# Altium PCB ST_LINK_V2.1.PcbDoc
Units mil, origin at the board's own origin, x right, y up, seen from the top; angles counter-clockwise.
Board outline 1520 x 655 mil, 2 copper layers (Top Layer, Bottom Layer); 53 components, 47 nets, 184 pads, 65 vias.
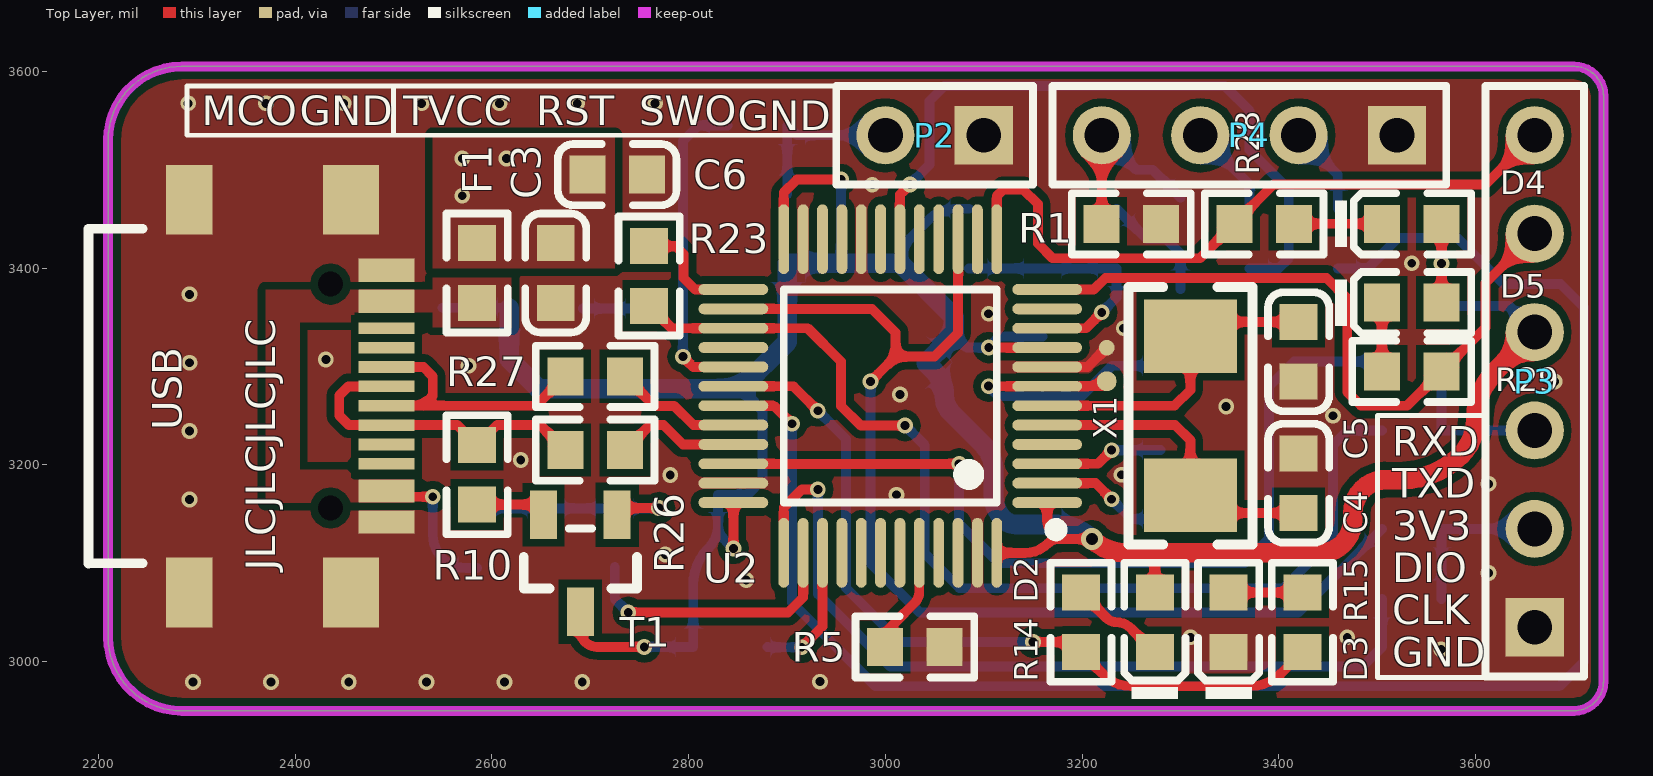
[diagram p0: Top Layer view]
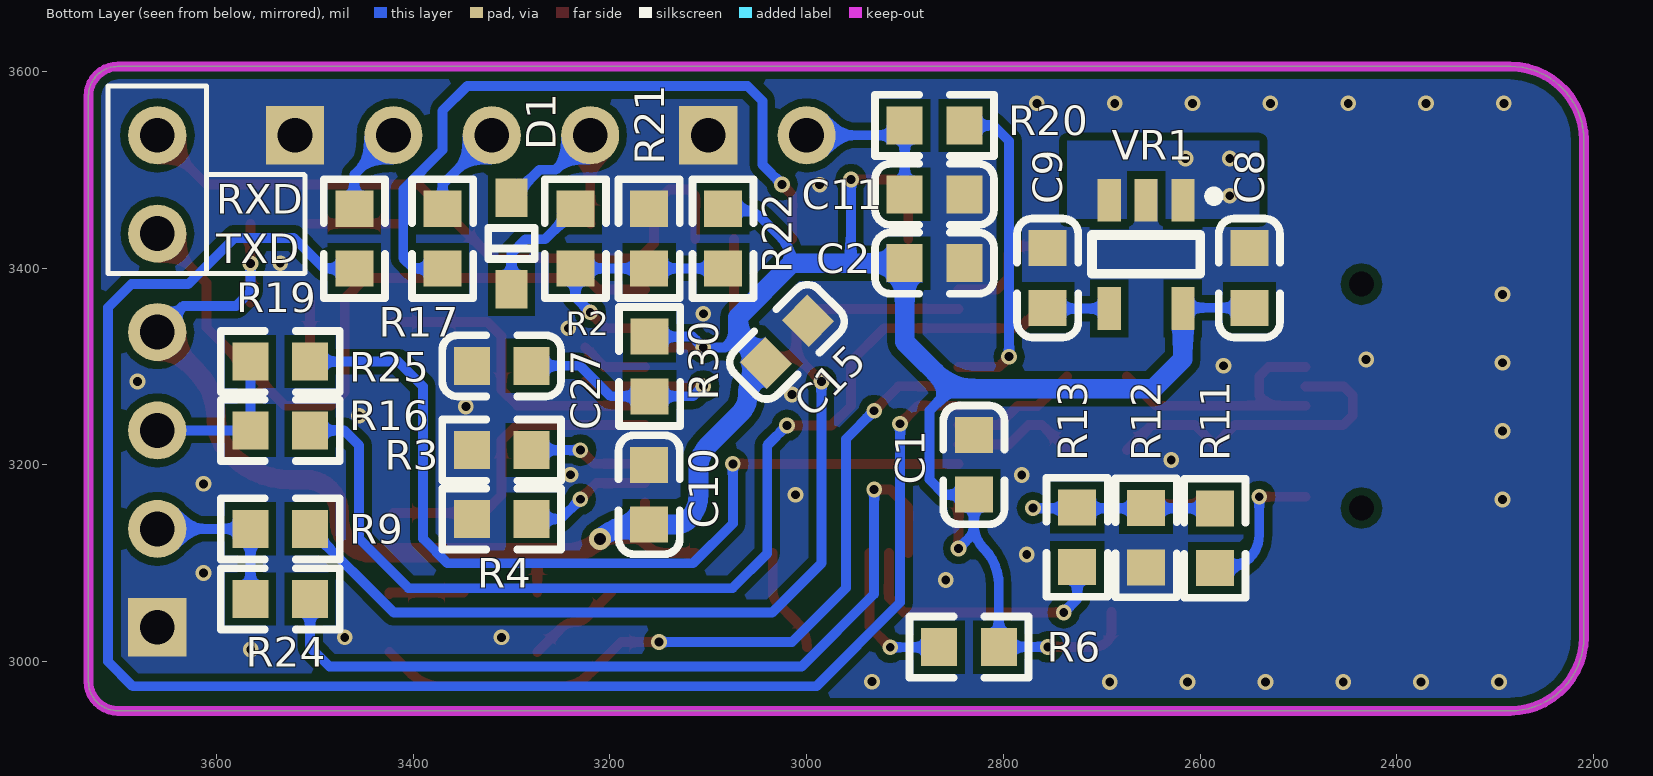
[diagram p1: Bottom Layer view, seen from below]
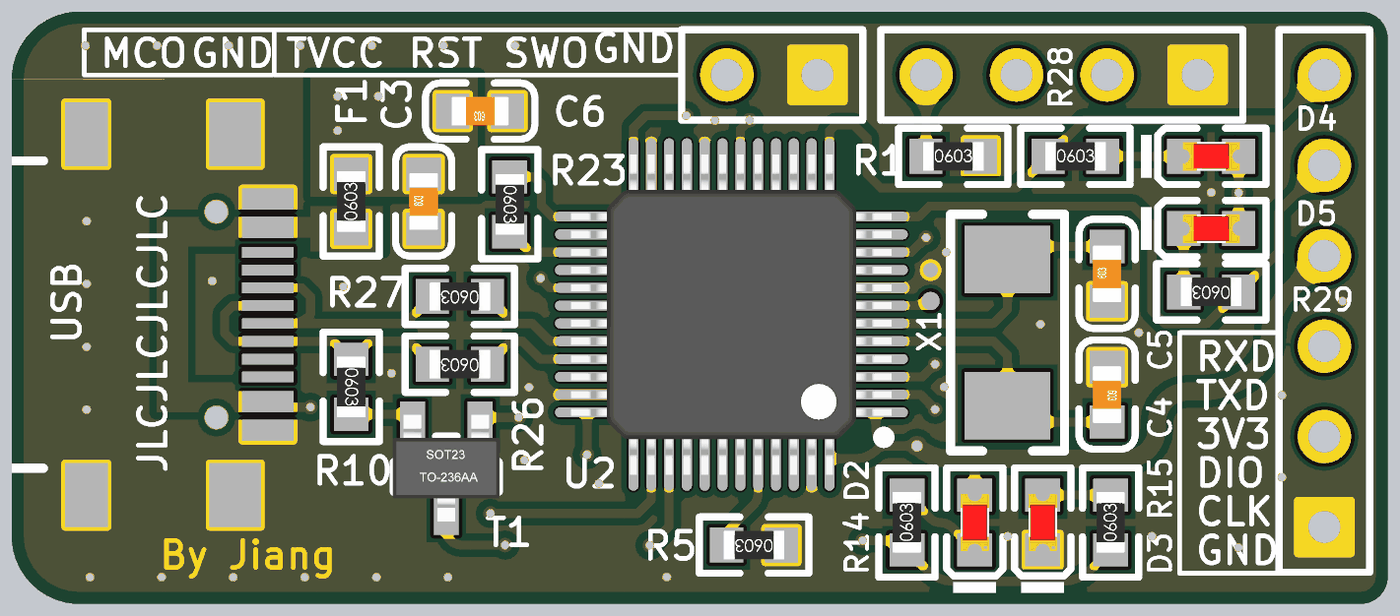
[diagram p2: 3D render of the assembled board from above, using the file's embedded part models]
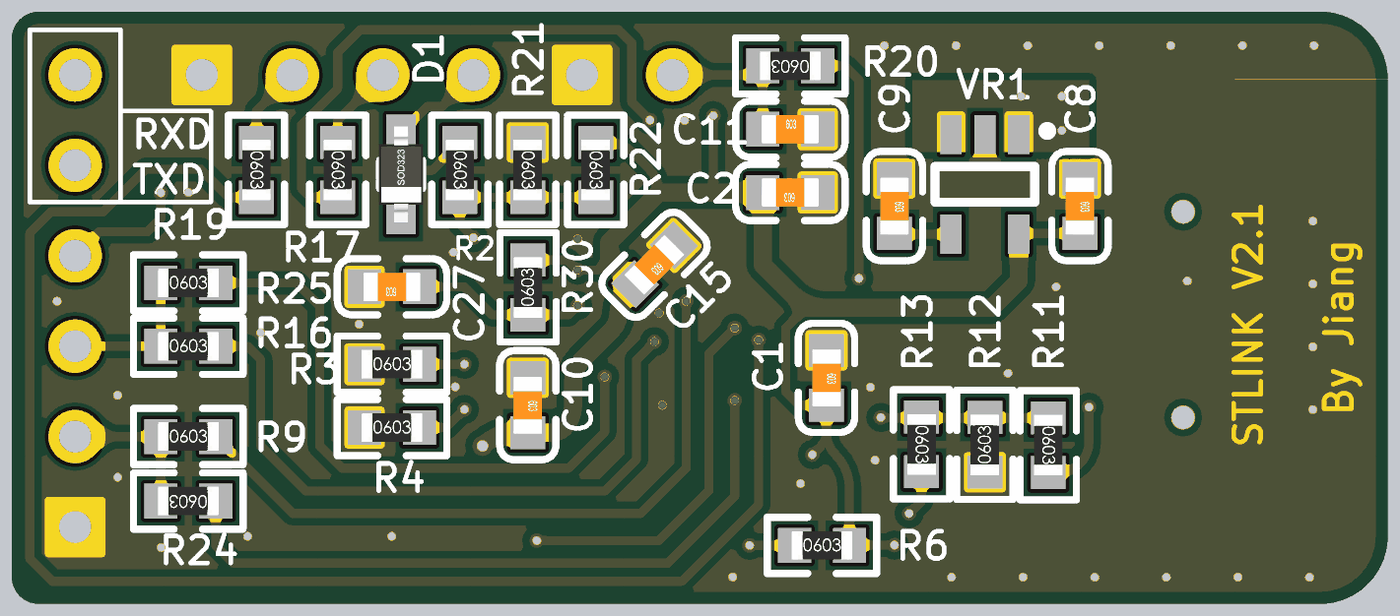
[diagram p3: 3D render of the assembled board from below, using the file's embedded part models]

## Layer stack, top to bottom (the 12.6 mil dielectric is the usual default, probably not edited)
Top Solder: solder mask 0.4, Solder Resist, Dk 3.5
Top Layer: signal copper 1.4
Dielectric 1: dielectric 12.6, FR-4, Dk 4.8
Bottom Layer: signal copper 1.4
Bottom Solder: solder mask 0.4, Solder Resist, Dk 3.5

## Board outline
2285,2950 cw(c2285,3025) 2210,3025 2210,3530 cw(c2285,3530) 2285,3605 3700,3605 cw(c3700,3575) 3730,3575 3730,2980 cw(c3700,2980) 3700,2950

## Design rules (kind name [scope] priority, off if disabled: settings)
Clearance [All] p1: gap=8 ignorepadtopadclearanceinfootprint=TRUE except(0: Arc-Hole Track-Hole SMDPad-Hole THPad-Hole Via-Hole Fill-Hole Poly-Hole Region-Hole Text-Hole)
PolygonConnect PolygonConnect_8 [All vs IsNamedPolygon('Top Layer-5V_USB_CHG 1') Or  IsNamedPolygon('Top Layer-5V_USB_CHG') Or  IsNamedPolygon('Bottom Layer-5V_USB_CHG') Or  IsNamedPolygon('Bottom Layer-GND') Or  IsNamedPolygon('Top Layer-GND') Or  IsNamedPolygon('Top Layer-5V_USB_CHG 2')] p1: connectstyle=Direct reliefconductorwidth=10 reliefentries=4 polygonreliefangle="90 Angle" airgapwidth=10
PolygonConnect PolygonConnect_7 [All vs IsNamedPolygon('Top Layer-5V_USB_CHG 2')] p2: connectstyle=Direct reliefconductorwidth=10 reliefentries=4 polygonreliefangle="90 Angle" airgapwidth=10
PolygonConnect PolygonConnect_6 [All vs IsNamedPolygon('Top Layer-5V_USB_CHG 1')] p3: connectstyle=Direct reliefconductorwidth=10 reliefentries=4 polygonreliefangle="90 Angle" airgapwidth=10
PolygonConnect PolygonConnect_5 [All vs IsNamedPolygon('Top Layer-No Net') Or  IsNamedPolygon('Top Layer-5V_USB_CHG') Or  IsNamedPolygon('Bottom Layer-No Net') Or  IsNamedPolygon('Bottom Layer-5V_USB_CHG') Or  IsNamedPolygon('Top Layer-5V_USB_CHG 2')] p4: connectstyle=Direct reliefconductorwidth=10 reliefentries=4 polygonreliefangle="90 Angle" airgapwidth=10
PolygonConnect PolygonConnect_4 [All vs IsNamedPolygon('Top Layer-5V_USB_CHG 2')] p5: connectstyle=Direct reliefconductorwidth=10 reliefentries=4 polygonreliefangle="90 Angle" airgapwidth=10
PolygonConnect PolygonConnect_3 [All vs IsNamedPolygon('Top Layer-5V_USB_CHG 1') Or  IsNamedPolygon('Top Layer-5V_USB_CHG') Or  IsNamedPolygon('Bottom Layer-5V_USB_CHG')] p6: connectstyle=Direct reliefconductorwidth=10 reliefentries=4 polygonreliefangle="90 Angle" airgapwidth=10
PolygonConnect PolygonConnect_2 [All vs IsNamedPolygon('Top Layer-5V_USB_CHG') Or  IsNamedPolygon('Top Layer-5V_USB_CHG 1')] p7: connectstyle=Direct reliefconductorwidth=10 reliefentries=4 polygonreliefangle="90 Angle" airgapwidth=10
PolygonConnect PolygonConnect_1 [All vs IsNamedPolygon('Top Layer-5V_USB_CHG 1') Or  IsNamedPolygon('Top Layer-5V_USB_CHG')] p8: connectstyle=Direct reliefconductorwidth=10 reliefentries=4 polygonreliefangle="90 Angle" airgapwidth=10
PolygonConnect [All] p9: connectstyle=Relief reliefconductorwidth=10 reliefentries=4 polygonreliefangle="90 Angle" airgapwidth=10
RoutingVias [All] p1: holewidth=28 width=50 viastyle="Through Hole" minholewidth=28 minwidth=50 maxholewidth=28 maxwidth=50
SolderMaskExpansion [All] p1: expansion=4
Width [All] p1: maxlimit=50 minlimit=10 preferedwidth=10
30 further rules are at their usual default settings.

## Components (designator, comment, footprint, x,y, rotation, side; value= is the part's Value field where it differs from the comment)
C1 "Capacitor" 0603_C 2830,3200 r270 bottom value=100nF
C2 "Capacitor" 0603_C 2870,3405 r0 bottom value=100nF
C3 "104" 0603_C 2665,3395 r90 top
C4 "Capacitor" 0603_C 3420,3181.42 r270 top value=20pF
C5 "Capacitor" 0603_C 3420,3315 r90 top value=20pF
C6 "104" 0603_C 2727.4,3495 r180 top
C8 "104" 0603_C 2550,3390 r270 bottom
C9 "104" 0603_C 2755,3390 r270 bottom
C10 "Capacitor" 0603_C 3160,3169.69 r270 bottom value=100nF
C11 "20pF" 0603_C 2870,3475 r180 bottom
C15 "Capacitor" 0603_C 3020,3325 r315 bottom value=100nF
C27 "Capacitor" 0603_C 3310,3300.68 r0 bottom value=103
D1 "BAT60JFILM" SOD-323 3300,3425 r90 bottom
D2 "绿灯 0603" 0603_LED_S1 3273.86,3040 r90 top
D3 "红灯 0603" 0603_LED_S1 3348.86,3040 r90 top
D4 "红灯 0603" 0603_LED_S1 3535,3445 r0 top
D5 "红灯 0603" 0603_LED_S1 3535,3365 r0 top
F1 "Fuse 2" 0603_R 2585,3395 r90 top
P2 "Header 2" HDR1X2 3100,3535 r180 top
P3 "Header 6" HDR1X6 3660,3035 r90 top
P4 "Header 4" HDR1X4 3520,3535 r180 top
R1 "Resistor" 0603_R 3250,3445 r0 top value=10K
R2 "100R" 0603_R 3235,3430 r270 bottom value=22R
R3 "N/A" 0603_R 3310,3215 r180 bottom value=10K
R4 "Resistor" 0603_R 3310,3145 r180 bottom value=10K
R5 "Resistor" 0603_R 3030,3015 r180 top value=100K
R6 "Resistor" 0603_R 2835,3014.69 r180 bottom value=4.7K
R9 "Resistor" 0603_R 3535,3135 r180 bottom value=22R
R10 "Resistor" 0603_R 2585,3190 r270 top value=1K5
R11 "Resistor" 0603_R 2585,3125.47 r270 bottom value=10K
R12 "Resistor" 0603_R 2655,3125.94 r90 bottom value=36K
R13 "Resistor" 0603_R 2725,3126.42 r270 bottom value=100R
R14 "Resistor" 0603_R 3198.86,3040 r90 top value=330R
R15 "Resistor" 0603_R 3423.86,3040 r90 top value=330R
R16 "Resistor" 0603_R 3535,3235 r180 bottom value=22R
R17 "Resistor" 0603_R 3370,3430 r270 bottom value=22R
R19 "Resistor" 0603_R 3459.74,3430 r270 bottom value=22R
R20 "Resistor" 0603_R 2870,3545 r0 bottom value=100R
R21 "Resistor" 0603_R 3160,3430 r270 bottom value=4K7
R22 "Resistor" 0603_R 3085,3430 r270 bottom value=4K7
R23 "Resistor" 0603_R 2760,3391.97 r270 top value=100R
R24 "Resistor" 0603_R 3535,3063.74 r0 bottom value=0R
R25 "Resistor" 0603_R 3535,3305 r180 bottom value=0R
R26 "Resistor" 0603_R 2705,3215 r180 top value=10R
R27 "Resistor" 0603_R 2705,3290 r180 top value=10R
R28 "Resistor" 0603_R 3385,3445 r0 top value=1K
R29 "Resistor" 0603_R 3535,3295 r180 top value=1K
R30 "Resistor" 0603_R 3159.69,3300 r90 bottom value=10K
T1 "9013-SOT23" SOT-23(SOT-23-3) 2690,3100 r90 top
U2 "STM32F103CBT6" LQFP-48_7x7x05P 3005,3270 r90 top locked
USB "TYPE-C 12P" "TYPE-C 12P 贴片" 2190,3440 r270 top locked
VR1 "SPX3819M5-L-3-3" SOT-23-5 2655,3414.02 r90 bottom
X1 "XTAL_8M_NX3225GD" SMD-5032_2P 3310,3250 r90 top locked value=8.00Mhz

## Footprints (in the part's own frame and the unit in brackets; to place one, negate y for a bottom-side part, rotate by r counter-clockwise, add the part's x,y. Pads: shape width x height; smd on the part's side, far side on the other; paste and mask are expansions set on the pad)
0603_C [mm]
  rect 0.93x0.98 smd: 1(-0.77,0) 2(0.77,0)
  silkscreen extent -1.53,-0.79 1.54,0.79, body extent -0.8,-0.4 0.8,0.4, height 0.3
0603_LED_S1 [mm]
  rect 0.93x0.98 smd: A(0.77,0) K(-0.77,0)
  silkscreen extent -1.98,-0.79 1.54,0.79, body extent -0.8,-0.4 0.8,0.4, height 0.6
0603_R [mm]
  rect 0.93x0.98 smd: 1(-0.77,0) 2(0.77,0)
  silkscreen extent -1.53,-0.79 1.54,0.79, body extent -0.85,-0.4 0.85,0.4, height 0.56
HDR1X2 [mm] "Connector; Header; 2 Position"
  rect 1.5x1.5 hole 0.9: 1(0,0)
  round 1.5 hole 0.9: 2(2.54,0)
  silkscreen extent -1.27,-1.27 3.81,1.27
HDR1X4 [mm] "Connector; Header; 4 Position"
  rect 1.5x1.5 hole 0.9: 1(0,0)
  round 1.5 hole 0.9: 2(2.54,0) 3(5.08,0) 4(7.62,0)
  silkscreen extent -1.27,-1.27 8.89,1.27
HDR1X6 [mm] "Connector; Header; 6 Position"
  rect 1.5x1.5 hole 0.9: 1(0,0)
  round 1.5 hole 0.9: 2(2.54,0) 3(5.08,0) 4(7.62,0) 5(10.16,0) 6(12.7,0)
  silkscreen extent -1.27,-1.27 13.97,1.27
LQFP-48_7x7x05P [mm]
  oval 0.28x1.8 smd mask+0.051: 1(-2.75,-4.05) 2(-2.25,-4.05) 3(-1.75,-4.05) 4(-1.25,-4.05) 5(-0.75,-4.05) 6(-0.25,-4.05) 7(0.25,-4.05) 8(0.75,-4.05) 9(1.25,-4.05) 10(1.75,-4.05) 11(2.25,-4.05) 12(2.75,-4.05) 25(2.75,4.05) 26(2.25,4.05) 27(1.75,4.05) 28(1.25,4.05) 29(0.75,4.05) 30(0.25,4.05) 31(-0.25,4.05) 32(-0.75,4.05) 33(-1.25,4.05) 34(-1.75,4.05) 35(-2.25,4.05) 36(-2.75,4.05)
  oval 1.8x0.28 smd mask+0.051: 13(4.05,-2.75) 14(4.05,-2.25) 15(4.05,-1.75) 16(4.05,-1.25) 17(4.05,-0.75) 18(4.05,-0.25) 19(4.05,0.25) 20(4.05,0.75) 21(4.05,1.25) 22(4.05,1.75) 23(4.05,2.25) 24(4.05,2.75) 37(-4.05,2.75) 38(-4.05,2.25) 39(-4.05,1.75) 40(-4.05,1.25) 41(-4.05,0.75) 42(-4.05,0.25) 43(-4.05,-0.25) 44(-4.05,-0.75) 45(-4.05,-1.25) 46(-4.05,-1.75) 47(-4.05,-2.25) 48(-4.05,-2.75)
  silkscreen extent -3.6,-4.42 2.75,2.75, body extent -4.5,-4.5 4.5,4.5, height 1.6
SMD-5032_2P [mm]
  rect 1.9x2.4 smd: 1(-2.05,0) 2(2.05,0)
  silkscreen extent -3.32,-1.6 3.32,1.6
SOD-323 [mm]
  rect 1x0.83 smd: 1(1.18,0) 2(-1.18,0)
  silkscreen extent -0.4,-0.6 0.4,0.6, body extent -1.35,-0.63 1.35,0.63, height 1.1
SOT-23(SOT-23-3) [mm]
  rect 1.25x0.7 smd: 1(1.25,-0.95) 2(1.25,0.95) 3(-1.25,0)
  silkscreen extent -0.65,-1.46 0.9,1.46, body extent -1.5,-1.5 1.5,1.5, height 1.3
SOT-23-5 [mm]
  rect 1.1x0.6 smd: 1(1.4,-0.95) 2(1.4,0) 3(1.4,0.95) 4(-1.4,0.95) 5(-1.4,-0.95)
  silkscreen extent -0.5,-1.87 1.62,1.4
"TYPE-C 12P 贴片" [mm]
  rect 1.8x1.45 smd: 0(-0.75,6.78) 0(9.39,6.78)
  rect 1.8x1.2 smd: 0(-0.75,2.6) 0(9.39,2.6)
  round 0 hole 0.65: 5(1.43,6.25) 5(7.21,6.25)
  rect 0.3x1.45 smd: A1(0.92,7.695) A4(1.72,7.695) A5(3.07,7.695) A6(4.07,7.695) A7(4.57,7.695) A8(5.57,7.695) A9(6.92,7.695) A12(7.72,7.695) B1(7.42,7.695) B4(6.62,7.695) B5(6.07,7.695) B6(5.07,7.695) B7(3.57,7.695) B8(2.57,7.695) B9(2.02,7.695) B12(1.22,7.695)
  silkscreen extent 0,0 8.64,1.4, body extent 0,0 8.64,8, height 3.21

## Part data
C1 C2 C10 C15 C27: library part MCD-00211, "Capacitor, MLCC, 100nF, 16V, X7R, 10%, 0603, T=0,8mm", Manufacturer=YAGEO, Manufacturer_Part_Number=CC0603KRX7R7BB104, Package=C0603
C3 C6 C8 C9: library part "0603 2.7pF (2R7) 0.25pF 50V", "贴片电容", Package=0603, SuppliersPartNumber=C16149
C4 C5: library part MCD-00637, "Capacitor, MLCC, 10pF, 50V, NPO, 5%, 0603, T=0,8mm", Manufacturer=YAGEO, Manufacturer_Part_Number=CC0603JRNPO9BN100, Package=C0603
C11: library part MCD-00638, "Capacitor, MLCC, 20pF, 50V, NPO, 5%, 0603, T=0,8mm", Manufacturer=YAGEO, Manufacturer_Part_Number=CC0603JRNPO9BN200, Package=C0603
D1: library part MCD-00034, Manufacturer=STMICROELECTRONICS
D2: library part "0603 绿灯", "发光二极管", Package=0603, SuppliersPartNumber=C72043
D3 D4 D5: library part "0603 红灯", "发光二极管", Package=0603, SuppliersPartNumber=C2286
F1: "Fuse"
P2: "Header, 2-Pin"
P3: "Header, 6-Pin"
P4: "Header, 4-Pin"
R1 R3 R4 R11: library part MCD-00220, "Resistor,10K,0603,1%,1/10W", Manufacturer=YAGEO, Manufacturer_Part_Number=RC0603FR-0710KL, Package=R0603
R2 R9 R16 R17 R19 R24 R25: library part MCD-00066, "Resistor,22R,0603,1%,1/10W", Manufacturer=YAGEO, Manufacturer_Part_Number=RC0603FR-0722RL, Package=R0603
R5 R30: library part MCD-00223, "Resistor,100K,0603,1%,1/10W", Manufacturer=YAGEO, Manufacturer_Part_Number=RC0603FR-07100KL, Package=R0603
R6 R14 R15 R28 R29: library part MCD-00197, "Resistor,330R,0603,1%,1/10W", Manufacturer=YAGEO, Manufacturer_Part_Number=RC0603FR-07330RL, Package=R0603
R10: library part MCD-00217, "Resistor,1K5,0603,1%,1/10W", Manufacturer=YAGEO, Manufacturer_Part_Number=RC0603FR-071K5L, Package=R0603
R12: library part MCD-00221, "Resistor,36K,0603,1%,1/10W", Manufacturer=YAGEO, Manufacturer_Part_Number=RC0603FR-0736KL, Package=R0603
R13 R20 R23 R26 R27: library part MCD-00224, "Resistor,100R,0603,1%,1/10W", Manufacturer=YAGEO, Manufacturer_Part_Number=RC0603FR-07100RL, Package=R0603
R21 R22: library part MCD-00219, "Resistor,4K7,0603,1%,1/10W", Manufacturer=YAGEO, Manufacturer_Part_Number=RC0603FR-074K7L, Package=R0603
T1: library part MCD-00073, "NPN Bipolar Transistor", Manufacturer=NXP, Manufacturer_Part_Number=BSR14
U2: library part MCD-00085, "Medium-density performance line ARM-based 32-bit MCU with 128KB Flash", Manufacturer=STMICROELECTRONICS
VR1: "LDO"
X1: library part MCD-00092, "Crystal 8Mhz, 8pF, -+50PPM, SMD", Manufacturer=NDK, Manufacturer_Part_Number="NX3225GD 8MHz EXS00A-CG04874"

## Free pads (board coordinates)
  round 20 smd: 9(3225,3285)
  round 16 smd: 10(3225,3319.13)

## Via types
v1: diameter 16, hole 9, Top Layer to Bottom Layer, tented both sides, 64 vias
v2: diameter 22, hole 12, Top Layer to Bottom Layer, tented both sides, 1 vias

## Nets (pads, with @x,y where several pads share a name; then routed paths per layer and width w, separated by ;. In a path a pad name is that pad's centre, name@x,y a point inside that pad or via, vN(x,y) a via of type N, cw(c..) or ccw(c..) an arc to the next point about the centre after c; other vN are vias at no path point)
3V3_STLK: C1.2 C2.2 C8.2 C10.2 C15.2 D2.A D4.A D5.A P3.4 R6.2 R22.1 R30.2 T1.3 U2.1 U2.9 U2.24 U2.36 U2.48 VR1.5 | length 3025.6
  Top Layer w10: T1.3 2690,3032.07 ccw(c2707.07,3032.07) 2695,3020 ccw(c2707.07,3032.07) 2707.07,3015 v1(2755,3015) ; v1(2845.55,3115.08) U2.36 ; U2.24 2896.73,3476.73 2910,3490 v1(2955,3490) ; v1(3105.08,3319.21) U2.9 ; U2.48 3142.19,3110.55 ccw(c3142.19,3142.81) 3165,3120 cw(c3176.31,3108.69) 3176.31,3124.69 3185,3124.69 ; U2.1 3164.45,3142.69 ccw(c3177.44,3142.69) 3168.25,3133.51 3171.47,3130.29 ccw(c3185,3143.82) 3185,3124.69 ; v2(3210,3124.69) 3185,3124.69 ; D2.A 3273.86,3110.55 ; D5.A v1(3565.31,3404.69) D4.A
  Top Layer w20: v2(3210,3124.69) ccw(c3244.12,3158.81) 3244.12,3110.55 3273.86,3110.55 3442.19,3110.55 ccw(c3442.19,3142.81) 3465,3120 ccw(c3440.86,3144.14) 3475,3144.14 3475,3150.86 cw(c3509.14,3150.86) 3485,3175 cw(c3509.14,3150.86) 3509.14,3185 3524.64,3185 ccw(c3524.64,3270.36) 3585,3210 ccw(c3548.79,3246.21) 3600,3246.21 cw(c3669.5,3246.21) 3620.36,3295.36 P3.4
  Bottom Layer w10: C8.2 2615.7,3359.69 cw(c2615.7,3357) VR1.5 ; v1(2755,3015) 2804.37,3015 R6.2 2804.68,3078.03 cw(c2856.97,3078.03) 2820,3115 ccw(c2795.86,3139.14) 2830,3139.14 ; v1(2845.55,3115.08) 2836.02,3124.61 cw(c2850.55,3139.14) 2830,3139.14 ; 2852.81,3277.5 2875,3255.31 2875,3185 2859.69,3169.69 C1.2 2830,3139.14 ; 2955,3405 v1(2955,3490) ; 3015,3405 cw(c3051.21,3405) 3025.61,3430.61 3045,3450 cw(c3069.9,3425.1) 3069.9,3460.31 R22.1 ; 3070,3332.13 3082.92,3319.21 v1(3105.08,3319.21) 3116.18,3330.32 R30.2 ; v1(3565.31,3404.69) 3565.31,3376.27 3580,3361.59 3633.41,3361.59 P3.4
  Bottom Layer w20: VR1.5 2617.6,3307.4 2647.5,3277.5 2852.81,3277.5 2900.31,3325 C2.2 2955,3405 3015,3405 3070,3350 3070,3332.13 C15.2 3049.39,3295.61 cw(c3023.79,3270) 3060,3270 ccw(c3084.14,3270) 3067.07,3252.93 3099.39,3220.61 cw(c3073.79,3195) 3110,3195 3110,3168.83 ccw(c3144.14,3168.83) 3120,3144.69 ccw(c3132.83,3157.52) 3132.83,3139.37 C10.2 3174.55,3139.37 cw(c3174.55,3089.23) v2(3210,3124.69)
5V_USB_CHG: F1.1 R11.2 USB.A4 USB.A9 USB.B4 USB.B9 | length 149.9
  Top Layer w10: USB.A9 v1(2540,3167.56)
  Bottom Layer w10: v1(2540,3167.56) 2540,3129.14 ccw(c2574.14,3129.14) 2550,3105 ccw(c2573.76,3128.76) 2573.76,3095.16 R11.2
AIN_1: R2.2 R21.2 R22.2 U2.10 | length 263.1
  Top Layer w10: U2.10 3203.9,3338.9 v1(3220,3355)
  Bottom Layer w10: R22.2 R21.2 R2.2 3235,3370 v1(3220,3355)
GND: C1.1 C2.1 C3.1 C4.1 C5.1 C6.1 C8.1 C9.1 C10.1 C11.2 C15.1 C27.2 D3.K P2.1 P3.1 P4.1 pad.10 R1.2 R3.1 R4.1 R5.1 R12.1 R21.1 U2.8 U2.20 U2.23 U2.35 U2.47 USB.0 USB.A1 USB.A12 USB.B1 USB.B12 VR1.2 | length 68.7
  Top Layer w10: U2.8 3205.39,3299.53 pad.10
  other v1: 2296.36,2979.43 2375.47,2979.43 2454.57,2979.43 2533.68,2979.43 2612.79,2979.43 2691.89,2979.43 2933.61,2979.69 3565,3012.29 3310.2,3024.69 3469.46,3024.69 2858.65,3083.1 3613.04,3090 2776.36,3108.9 2292.72,3164.85 3011.36,3169.69 3613.04,3180.71 2781.36,3189.69 3240,3190 2629.48,3204.97 2292.72,3234.33 3455,3250 3346.36,3259.31 3014.83,3271.6 3680,3284.69 2576.36,3300.68 2292.72,3303.81 2431.36,3307.09 3242.2,3338.9 3104.99,3353.61 2292.72,3373.29 3535,3405 2986.78,3484.69 2291.36,3567.47 2370.47,3567.47 2449.57,3567.47 2528.68,3567.47 2607.79,3567.47 2686.89,3567.47 2766,3567.47
LED_STLK: R14.1 R15.1 U2.30 | length 804.1
  Top Layer w10: U2.30 2906.57,3279.84 v1(2931.42,3255) ; v1(3150,3020) 3188.54,3020 R14.1 3222.21,2986.34 ccw(c3249.58,3013.71) 3249.58,2975 3370.86,2975 ccw(c3370.86,3019.22) 3402.12,2987.95 R15.1
  Bottom Layer w10: v1(2931.42,3255) 2960,3226.42 2960,3075 3015,3020 v1(3150,3020)
MCO: C11.1 P2.2 R20.2 | length 173.8
  Bottom Layer w10: C11.1 R20.2 2910.32,3535 P2.2
NetC3_2: C3.2 C6.2 F1.2 VR1.1 VR1.3
  other v1: 2570,3473.46 2570,3511.32 2615,3511.32
NetC9_2: C9.2 VR1.4 | length 62.8
  Bottom Layer w10: VR1.4 2753.1,3358.9 ccw(c2753.1,3361.59) C9.2
NetD1_2: D1.2 R2.1 | length 120.2
  Bottom Layer w10: R2.1 3265.94,3429.37 3285.63,3429.37 3300,3415 D1.2
NetD2_K: D2.K R14.2 | length 98.6
  Top Layer w10: R14.2 3225.05,3044.12 ccw(c3235,3054.07) 3235,3040 cw(c3235,3019.37) 3249.58,3033.97 D2.K
NetD3_A: D3.A R15.2 | length 76.5
  Top Layer w10: D3.A R15.2 R15.2@3423.86,3068.86
NetD4_K: D4.K R28.2 | length 89.4
  Top Layer w10: R28.2 D4.K
NetD5_K: D5.K R29.2 | length 70
  Top Layer w10: R29.2 D5.K
NetD6_A: 
NetP3_1: P3.3 R16.1 R25.1 | length 164.7
  Bottom Layer w10: R25.1 R16.1 P3.3
NetP3_2: P3.2 R9.1 R24.2 | length 165.9
  Bottom Layer w10: R24.2 R9.1 P3.2
NetP4_2: P4.2 R19.1 | length 91.1
  Bottom Layer w10: P4.2 3459.74,3495.26 R19.1
NetP4_3: P4.3 R17.1 | length 95.4
  Bottom Layer w10: P4.3 3370,3485 R17.1
NetR3_2: R3.2 U2.3 | length 121
  Top Layer w10: U2.3 3216.1,3201.1 v1(3230,3215)
  Bottom Layer w10: v1(3230,3215) R3.2
NetR4_2: R4.2 U2.2 | length 130.3
  Top Layer w10: U2.2 3213.58,3181.42 v1(3230,3165)
  Bottom Layer w10: v1(3230,3165) 3250,3145 R4.2
NetR5_2: R5.2 U2.44 | length 107.8
  Top Layer w10: R5.2 cw(c3035.14,3015) 3010.07,3040.07 3030,3060 ccw(c3019.07,3070.93) 3034.53,3070.93 U2.44
NetR6_1: R6.1 U2.39 | length 139.4
  Top Layer w10: v1(2915,3014.69) 2936.1,3035.79 U2.39
  Bottom Layer w10: R6.1@2880.31,3015 2880.63,3014.69 v1(2915,3014.69)
NetR10_2: R10.2 T1.2 | length 71.9
  Top Layer w10: R10.2 2642.13,3159.68 T1.2
NetR11_1: R11.1 R12.2 R13.1 T1.1 | length 230.6
  Top Layer w10: T1.1 2734.33,3156.14 v1(2770,3156.14)
  Bottom Layer w10: R11.1 2769.65,3155.79 v1(2770,3156.14)
NetR20_1: R20.1 U2.29 | length 326.9
  Top Layer w10: v1(2794.21,3310) 2804.68,3299.53 U2.29
  Bottom Layer w10: v1(2794.21,3310) 2794.21,3529.21 2810,3545 R20.1
NetR26_1: R26.1 U2.33 | length 128.9
  Top Layer w10: R26.1 2760.79,3240.47 2774.53,3240.47 2794.21,3220.79 U2.33
NetR27_1: R27.1 U2.32 | length 130.8
  Top Layer w10: R27.1 2765.31,3260 2785.46,3260 2804.98,3240.47 U2.32
OSC_IN: C4.2 U2.5 X1.1 | length 325.2
  Top Layer w10: U2.5 3294.53,3240.47 3310,3225 X1.1 3328.19,3151.1 C4.2
OSC_OUT: C5.2 U2.6 X1.2 | length 322.8
  Top Layer w10: U2.6 3294.02,3260.16 3310,3276.14 X1.2 3324.61,3345.31 C5.2
PWR_ENn: U2.28
STL_USB_D_N: R27.2 USB.A7 USB.B7 | length 279.1
  Top Layer w10: USB.A7 2530.08,3260.08 ; USB.B7 2530.55,3299.45 2540,3290 2540,3270 2530.08,3260.08 ; R27.2 2644.76,3260.08 2530.08,3260.08
STL_USB_D_P: R10.1 R26.2 USB.A6 USB.B6 | length 333.2
  Top Layer w10: USB.A6 2454.13,3279.76 2445,3270.63 2445,3250 2454.61,3240.39 USB.B6 2564.92,3240.39 R10.1 2585.31,3220.31 2605.47,3240.47 2649.21,3240.47 R26.2
STLK_RX: P3.6 R28.1 U2.13 | length 697.5
  Top Layer w10: U2.13 3113.27,3473.27 3120,3480 3140,3480 3155,3465 3155,3425 3170,3410 3319.69,3410 R28.1 3394.69,3485 3610,3485 P3.6
STLK_TX: P3.5 R29.1 U2.12 | length 708.6
  Top Layer w10: U2.12 3211.85,3378.27 3223.58,3390 3448.27,3390 3469.46,3368.8 3469.46,3274.24 3483.54,3260.16 3530.47,3260.16 R29.1 3610,3339.69 3610,3385 P3.5
STM_JTCK: R24.1 U2.37 | length 855.8
  Top Layer w10: U2.37 2896.73,3156.73 2915,3175 v1(2931.42,3175)
  Bottom Layer w10: v1(2931.42,3175) 2931.42,3068.58 3005,2995 3485,2995 3504.69,3014.69 R24.1
STM_JTMS: R25.2 U2.34 | length 912.1
  Top Layer w10: U2.34 2845.63,3201.02 v1(3075,3201.02)
  Bottom Layer w10: v1(3075,3201.02) 3075,3140.31 3115.31,3100 3365,3100 3390,3125 3390,3279.69 3415.31,3305 R25.2
STM_RST: C27.1 pad.9 R30.1 U2.7 | length 314.4
  Top Layer w10: v1(3105,3280) 3164.29,3280 U2.7 3219.84,3279.84 pad.9
  Bottom Layer w10: v1(3105,3280) 3115.31,3269.69 R30.1 3199.08,3269.69 3230.08,3300.68 C27.1 ; R30.1@3159.37,3280 R30.1@3159.69,3279.69
T_JRST: U2.19
T_JTCK: R9.2 U2.15 U2.26 | length 1164.5
  Top Layer w10: U2.26 2986.42,3358.58 3010.31,3334.69 3010.31,3310 ; v1(2985,3284.69) 3010.31,3310 ; U2.15 3073.9,3333.9 3050,3310 3010.31,3310
  Bottom Layer w10: v1(2985,3284.69) 2985,3100 3035,3050 3419.68,3050 R9.2
T_JTDI: U2.17
T_JTDO: U2.16
T_JTMS: R16.2 R23.2 U2.27 | length 1076.4
  Top Layer w10: R23.2 2782.76,3338.9 U2.27 2921.1,3338.9 2955,3305 2955,3260 2975,3240 v1(3020,3240)
  Bottom Layer w10: v1(3020,3240) 3040,3220 3040,3110 3075.31,3074.69 3404.69,3074.69 3455,3125 3455,3220 3470,3235 R16.2
T_NRST: R17.2 U2.18 | length 705.5
  Top Layer w10: U2.18 3014.84,3474.84 v1(3025,3485)
  Bottom Layer w10: v1(3025,3485) 3045,3505 3045,3570 3060,3585 3345,3585 3370,3560 3370,3520 3410,3480 3410,3410 3399.68,3399.68 R17.2
T_SWDIO_IN: R23.1 U2.25 | length 118
  Top Layer w10: R23.1 2786.93,3422.28 2795,3414.21 2795,3389.98 2806.72,3378.27 U2.25
T_SWO: R19.2 U2.31 | length 1751.7
  Top Layer w10: U2.31 2886.57,3260.16 v1(2905,3241.73)
  Bottom Layer w10: v1(2905,3241.73) 2905,3060 2990,2975 3685,2975 3710,3000 3710,3360 3686.3,3383.7 3628.45,3383.7 3581.54,3430.61 3521.24,3430.61 3490.32,3399.68 R19.2
T_VCC: D1.1 P4.4 R1.1 | length 196.5
  Top Layer w10: R1.1 3220,3445.31 P4.4
  Bottom Layer w10: P4.4 3255,3500 3271.46,3500 D1.1
USB_RENUMn: R13.2 U2.38 | length 281.1
  Top Layer w10: v1(2738.74,3050) 2901.14,3050 2916.42,3065.28 U2.38
  Bottom Layer w10: R13.2 2725,3063.74 v1(2738.74,3050)
pads on no net: U2.4 U2.11 U2.14 U2.21 U2.22 U2.40 U2.41 U2.42 U2.43 U2.45 U2.46 USB.5 USB.A5 USB.A8 USB.B5 USB.B8

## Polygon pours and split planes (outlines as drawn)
GND on Top Layer "Top Layer-GND" (solid, pour order 11): 2210,3025 2210,3530 cw(c2285,3530) 2285,3605 3700,3605 cw(c3700,3575) 3730,3575 3730,2980 cw(c3700,2980) 3700,2950 2285,2950 cw(c2285,3025)
5V_USB_CHG on Top Layer "Top Layer-5V_USB_CHG 1" (solid, pour order 1): 2464.91,3378.09 2540,3378.09 2540,3390 2620,3390 2620,3340 2540,3340 2540,3355 2464.91,3355
5V_USB_CHG on Top Layer "Top Layer-5V_USB_CHG" (solid, pour order 0): 2520,3378.06 2370,3378.06 2370,3161.73 2520,3161.73 2520,3185 2460,3185 2460,3195 2405,3195 2405,3345 2460,3345 2460,3355 2520,3355
NetC3_2 on Top Layer "Top Layer-5V_USB_CHG 2" (solid, pour order 2): 2540,3400 2725,3400 2725,3535 2540,3535
GND on Bottom Layer "Bottom Layer-GND" (solid, pour order 13): 2210,3025 2210,3530 cw(c2285,3530) 2285,3605 3700,3605 cw(c3700,3575) 3730,3575 3730,2980 cw(c3700,2980) 3700,2950 2285,2950 cw(c2285,3025)
NetC3_2 on Bottom Layer "Bottom Layer-5V_USB_CHG" (solid, pour order 3): 2540,3529.21 2540,3450 2735,3450 2735,3529.21

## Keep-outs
Keep-Out Layer:
  the board outline again, w10

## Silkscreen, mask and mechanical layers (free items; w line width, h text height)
Top Overlay:
  lines w5: 2500,3535 2500,3585 ; 2950,3535 2290,3535 2290,3585 2950,3585 ; 3608.9,2983.9 3500,2983.9 3500,3250 3610,3250
  text "MCO" at 2305,3545 h30
  text "GND" at 2405,3545 h30
  text "TVCC" at 2510,3545 h30
  text "RST" at 2645,3545 h30
  text "SWO" at 2750,3545 h30
  text "GND" at 2850,3540 h30
  text "RXD" at 3515,3209.17 h30
  text "TXD" at 3515,3166.34 h30
  text "3V3" at 3515,3123.5 h30
  text "JLCJLCJLCJLC" at 2380,3092.2 h30 r90
  text "DIO" at 3515,3080.67 h30
  text "CLK" at 3515,3037.83 h30
  text "GND" at 3515,2995 h30
Bottom Overlay:
  lines w5: 3610,3394.67 3610,3495 ; 3610,3495 3610,3585 3710,3585 3710,3394.33 3510.67,3394.33 3510,3395 3510,3494.33 3510.67,3495 3610,3495
  text "RXD" at 3600,3455 h30
  text "TXD" at 3600,3405 h30
Top Solder:
  text "By Jiang" at 2370.47,2990 h30
Bottom Solder:
  text "By Jiang" at 2250,3155.31 h30 r270
  text "STLINK V2.1" at 2350,3120 h30 r270
Mechanical 1:
  lines w5: 2285,3605 ccw(c2285,3530) 2210,3530 2210,3025 ccw(c2285,3025) 2285,2950 3700,2950 ; 2285,3605 3700,3605 ; 2285,3605 2285,3605 ; 3700,2950 ccw(c3700,2980) 3730,2980 3730,3575 ccw(c3700,3575) 3700,3605 ; 3700,2950 3700,2950 ; 3700,3605 3700,3605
